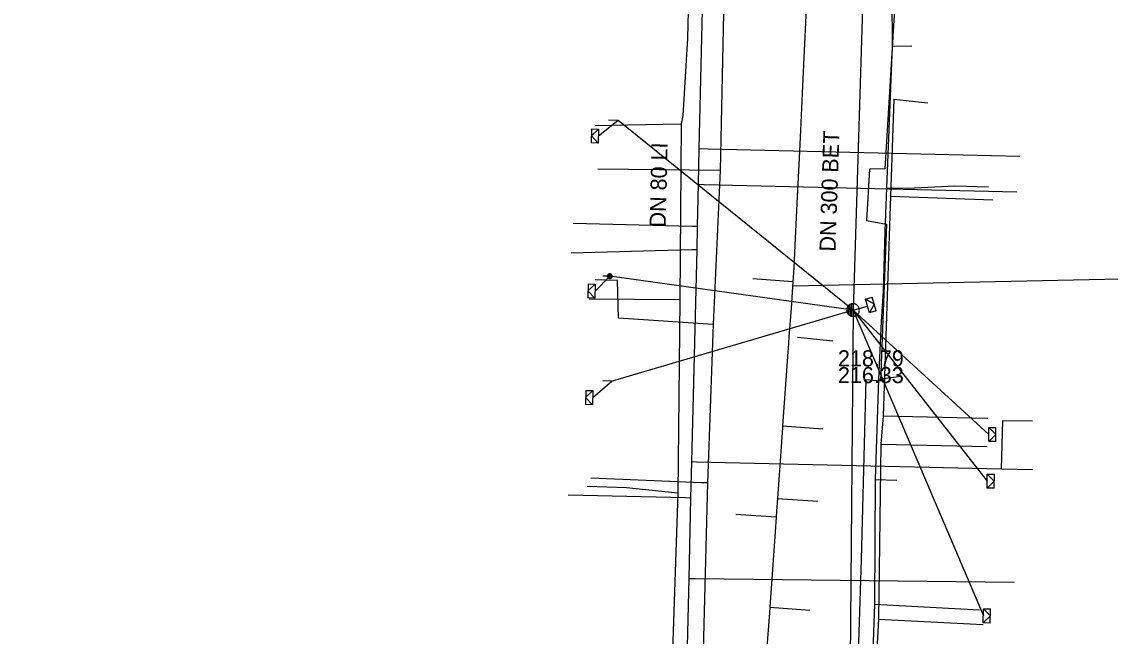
# Model space of a CAD drawing. Extents: x -596024 to -594475, y -1163820 to -1161957.
# Drawn here: x -595840.9 to -595786.8, y -1163039.3 to -1163008.8 of the extents above; entities that cross this region are included whole.
import ezdxf

# ---------------------------------------------------------------- set-up
doc = ezdxf.new("R2010")
doc.units = 0
for name, color, linetype in [('13', 7, 'Continuous'), ('31', 7, 'Continuous'), ('Vrstva 12', 7, 'Continuous'), ('Vrstva 13', 7, 'Continuous'), ('Vrstva 15', 7, 'Continuous'), ('Vrstva 16', 7, 'Continuous'), ('Vrstva 25', 7, 'Continuous'), ('Vrstva 43', 7, 'Continuous'), ('Vrstva 51', 7, 'Continuous'), ('Vrstva 55', 7, 'Continuous'), ('Vrstva 9', 7, 'Continuous')]:
    doc.layers.add(name, color=color, linetype=linetype)

# ---------------------------------------------------------------- blocks, each defined once
blk = doc.blocks.new('NN630')
at = {"layer": '31'}
for points in [[(-0.003, -0.7), (-0.703, 0)], [(-0.703, -0.7), (-0.703, 0), (0.697, 0), (0.697, -0.7)], [(-0.003, -0.7), (0.697, 0)], [(-0.703, -0.7), (0.697, -0.7)]]:
    blk.add_lwpolyline(points, dxfattribs=at)
blk = doc.blocks.new('NN510')
at = {"layer": '13'}
blk.add_lwpolyline([(0.001, 0.002), (0.001, 0.939)], dxfattribs=at)
blk = doc.blocks.new('NN500')
at = {"layer": '13'}
for points in [[(-0.001, -0.235), (0.023, -0.234), (0.048, -0.23), (0.071, -0.224), (0.094, -0.215), (0.116, -0.204), (0.137, -0.191), (0.156, -0.175), (0.173, -0.158), (0.189, -0.139), (0.202, -0.118), (0.213, -0.096), (0.222, -0.073), (0.229, -0.049), (0.232, -0.025), (0.234, 0), (0.232, 0.024), (0.229, 0.048), (0.222, 0.072), (0.213, 0.095), (0.202, 0.117), (0.189, 0.138), (0.173, 0.157), (0.156, 0.174), (0.137, 0.19), (0.116, 0.203), (0.094, 0.214), (0.071, 0.223), (0.048, 0.229), (0.023, 0.233), (-0.001, 0.235), (-0.026, 0.233), (-0.05, 0.229), (-0.074, 0.223), (-0.097, 0.214), (-0.119, 0.203), (-0.139, 0.19), (-0.158, 0.174), (-0.176, 0.157), (-0.191, 0.138), (-0.205, 0.117), (-0.216, 0.095), (-0.225, 0.072), (-0.231, 0.048), (-0.235, 0.024), (-0.236, 0), (-0.235, -0.025), (-0.231, -0.049), (-0.225, -0.073), (-0.216, -0.096), (-0.205, -0.118), (-0.191, -0.139), (-0.176, -0.158), (-0.158, -0.175), (-0.139, -0.191), (-0.119, -0.204), (-0.097, -0.215), (-0.074, -0.224), (-0.05, -0.23), (-0.026, -0.234), (-0.001, -0.235)], [(-0.001, -0.235), (0.023, -0.234), (0.048, -0.23), (0.071, -0.224), (0.094, -0.215), (0.116, -0.204), (0.137, -0.191), (0.156, -0.175), (0.173, -0.158), (0.189, -0.139), (0.202, -0.118), (0.213, -0.096), (0.222, -0.073), (0.229, -0.049), (0.232, -0.025), (0.234, 0), (0.232, 0.024), (0.229, 0.048), (0.222, 0.072), (0.213, 0.095), (0.202, 0.117), (0.189, 0.138), (0.173, 0.157), (0.156, 0.174), (0.137, 0.19), (0.116, 0.203), (0.094, 0.214), (0.071, 0.223), (0.048, 0.229), (0.023, 0.233), (-0.001, 0.235), (-0.026, 0.233), (-0.05, 0.229), (-0.074, 0.223), (-0.097, 0.214), (-0.119, 0.203), (-0.139, 0.19), (-0.158, 0.174), (-0.176, 0.157), (-0.191, 0.138), (-0.205, 0.117), (-0.216, 0.095), (-0.225, 0.072), (-0.231, 0.048), (-0.235, 0.024), (-0.236, 0), (-0.235, -0.025), (-0.231, -0.049), (-0.225, -0.073), (-0.216, -0.096), (-0.205, -0.118), (-0.191, -0.139), (-0.176, -0.158), (-0.158, -0.175), (-0.139, -0.191), (-0.119, -0.204), (-0.097, -0.215), (-0.074, -0.224), (-0.05, -0.23), (-0.026, -0.234), (-0.001, -0.235)], [(-0.001, -0.206), (0.02, -0.205), (0.041, -0.201), (0.062, -0.196), (0.082, -0.188), (0.101, -0.178), (0.12, -0.167), (0.136, -0.153), (0.151, -0.138), (0.165, -0.121), (0.177, -0.103), (0.186, -0.084), (0.194, -0.064), (0.2, -0.043), (0.203, -0.022), (0.204, 0), (0.203, 0.021), (0.2, 0.042), (0.194, 0.063), (0.186, 0.083), (0.177, 0.102), (0.165, 0.12), (0.151, 0.137), (0.136, 0.152), (0.12, 0.166), (0.101, 0.177), (0.082, 0.187), (0.062, 0.195), (0.041, 0.2), (0.02, 0.204), (-0.001, 0.205), (-0.023, 0.204), (-0.044, 0.2), (-0.065, 0.195), (-0.085, 0.187), (-0.104, 0.177), (-0.122, 0.166), (-0.139, 0.152), (-0.154, 0.137), (-0.167, 0.12), (-0.179, 0.102), (-0.189, 0.083), (-0.197, 0.063), (-0.202, 0.042), (-0.205, 0.021), (-0.207, 0), (-0.205, -0.022), (-0.202, -0.043), (-0.197, -0.064), (-0.189, -0.084), (-0.179, -0.103), (-0.167, -0.121), (-0.154, -0.138), (-0.139, -0.153), (-0.122, -0.167), (-0.104, -0.178), (-0.085, -0.188), (-0.065, -0.196), (-0.044, -0.201), (-0.023, -0.205), (-0.001, -0.206)], [(-0.001, -0.176), (0.017, -0.175), (0.035, -0.172), (0.053, -0.168), (0.07, -0.161), (0.087, -0.153), (0.102, -0.143), (0.116, -0.131), (0.129, -0.118), (0.141, -0.104), (0.151, -0.088), (0.159, -0.072), (0.166, -0.055), (0.171, -0.037), (0.174, -0.019), (0.175, 0), (0.174, 0.018), (0.171, 0.036), (0.166, 0.054), (0.159, 0.071), (0.151, 0.087), (0.141, 0.103), (0.129, 0.117), (0.116, 0.13), (0.102, 0.142), (0.087, 0.152), (0.07, 0.16), (0.053, 0.167), (0.035, 0.172), (0.017, 0.174), (-0.001, 0.175), (-0.02, 0.174), (-0.038, 0.172), (-0.056, 0.167), (-0.073, 0.16), (-0.089, 0.152), (-0.105, 0.142), (-0.119, 0.13), (-0.132, 0.117), (-0.143, 0.103), (-0.153, 0.087), (-0.162, 0.071), (-0.168, 0.054), (-0.173, 0.036), (-0.176, 0.018), (-0.177, 0), (-0.176, -0.019), (-0.173, -0.037), (-0.168, -0.055), (-0.162, -0.072), (-0.153, -0.088), (-0.143, -0.104), (-0.132, -0.118), (-0.119, -0.131), (-0.105, -0.143), (-0.089, -0.153), (-0.073, -0.161), (-0.056, -0.168), (-0.038, -0.172), (-0.02, -0.175), (-0.001, -0.176)], [(-0.001, -0.147), (0.014, -0.146), (0.029, -0.143), (0.044, -0.139), (0.058, -0.134), (0.072, -0.127), (0.085, -0.119), (0.097, -0.109), (0.107, -0.098), (0.117, -0.086), (0.125, -0.073), (0.132, -0.06), (0.138, -0.046), (0.142, -0.031), (0.144, -0.016), (0.145, 0), (0.144, 0.015), (0.142, 0.03), (0.138, 0.045), (0.132, 0.059), (0.125, 0.073), (0.117, 0.086), (0.107, 0.097), (0.097, 0.108), (0.085, 0.118), (0.072, 0.126), (0.058, 0.133), (0.044, 0.139), (0.029, 0.143), (0.014, 0.145), (-0.001, 0.146), (-0.017, 0.145), (-0.032, 0.143), (-0.046, 0.139), (-0.061, 0.133), (-0.074, 0.126), (-0.087, 0.118), (-0.099, 0.108), (-0.11, 0.097), (-0.119, 0.086), (-0.128, 0.073), (-0.135, 0.059), (-0.14, 0.045), (-0.144, 0.03), (-0.147, 0.015), (-0.147, 0), (-0.147, -0.016), (-0.144, -0.031), (-0.14, -0.046), (-0.135, -0.06), (-0.128, -0.073), (-0.119, -0.086), (-0.11, -0.098), (-0.099, -0.109), (-0.087, -0.119), (-0.074, -0.127), (-0.061, -0.134), (-0.046, -0.139), (-0.032, -0.143), (-0.017, -0.146), (-0.001, -0.147)], [(-0.001, -0.117), (0.011, -0.116), (0.023, -0.114), (0.035, -0.111), (0.046, -0.107), (0.057, -0.101), (0.067, -0.095), (0.077, -0.087), (0.085, -0.078), (0.093, -0.069), (0.1, -0.059), (0.105, -0.048), (0.11, -0.036), (0.113, -0.025), (0.115, -0.013), (0.115, 0), (0.115, 0.012), (0.113, 0.024), (0.11, 0.036), (0.105, 0.047), (0.1, 0.058), (0.093, 0.068), (0.085, 0.078), (0.077, 0.086), (0.067, 0.094), (0.057, 0.101), (0.046, 0.106), (0.035, 0.11), (0.023, 0.114), (0.011, 0.116), (-0.001, 0.116), (-0.013, 0.116), (-0.025, 0.114), (-0.037, 0.11), (-0.049, 0.106), (-0.059, 0.101), (-0.07, 0.094), (-0.079, 0.086), (-0.088, 0.078), (-0.096, 0.068), (-0.102, 0.058), (-0.108, 0.047), (-0.112, 0.036), (-0.115, 0.024), (-0.117, 0.012), (-0.118, 0), (-0.117, -0.013), (-0.115, -0.025), (-0.112, -0.036), (-0.108, -0.048), (-0.102, -0.059), (-0.096, -0.069), (-0.088, -0.078), (-0.079, -0.087), (-0.07, -0.095), (-0.059, -0.101), (-0.049, -0.107), (-0.037, -0.111), (-0.025, -0.114), (-0.013, -0.116), (-0.001, -0.117)], [(-0.001, -0.087), (0.008, -0.087), (0.017, -0.085), (0.026, -0.083), (0.034, -0.08), (0.042, -0.076), (0.05, -0.071), (0.057, -0.065), (0.063, -0.059), (0.069, -0.051), (0.074, -0.044), (0.078, -0.036), (0.081, -0.027), (0.084, -0.019), (0.085, -0.01), (0.086, 0), (0.085, 0.009), (0.084, 0.018), (0.081, 0.026), (0.078, 0.035), (0.074, 0.043), (0.069, 0.051), (0.063, 0.058), (0.057, 0.064), (0.05, 0.07), (0.042, 0.075), (0.034, 0.079), (0.026, 0.082), (0.017, 0.085), (0.008, 0.086), (-0.001, 0.087), (-0.01, 0.086), (-0.019, 0.085), (-0.028, 0.082), (-0.037, 0.079), (-0.045, 0.075), (-0.052, 0.07), (-0.059, 0.064), (-0.066, 0.058), (-0.072, 0.051), (-0.077, 0.043), (-0.081, 0.035), (-0.084, 0.026), (-0.086, 0.018), (-0.088, 0.009), (-0.088, 0), (-0.088, -0.01), (-0.086, -0.019), (-0.084, -0.027), (-0.081, -0.036), (-0.077, -0.044), (-0.072, -0.052), (-0.066, -0.059), (-0.059, -0.065), (-0.052, -0.071), (-0.045, -0.076), (-0.037, -0.08), (-0.028, -0.083), (-0.019, -0.085), (-0.01, -0.087), (-0.001, -0.087)], [(-0.001, -0.058), (0.005, -0.057), (0.011, -0.056), (0.016, -0.055), (0.022, -0.053), (0.027, -0.05), (0.032, -0.047), (0.037, -0.043), (0.041, -0.039), (0.045, -0.034), (0.048, -0.029), (0.051, -0.024), (0.053, -0.018), (0.055, -0.012), (0.056, -0.006), (0.056, 0), (0.056, 0.006), (0.055, 0.011), (0.053, 0.017), (0.051, 0.023), (0.048, 0.028), (0.045, 0.033), (0.041, 0.038), (0.037, 0.042), (0.032, 0.046), (0.027, 0.049), (0.022, 0.052), (0.016, 0.054), (0.011, 0.056), (0.005, 0.057), (-0.001, 0.057), (-0.007, 0.057), (-0.013, 0.056), (-0.019, 0.054), (-0.025, 0.052), (-0.03, 0.049), (-0.035, 0.046), (-0.04, 0.042), (-0.044, 0.038), (-0.048, 0.033), (-0.051, 0.028), (-0.054, 0.023), (-0.056, 0.017), (-0.057, 0.011), (-0.058, 0.006), (-0.059, 0), (-0.058, -0.006), (-0.057, -0.012), (-0.056, -0.018), (-0.054, -0.024), (-0.051, -0.029), (-0.048, -0.034), (-0.044, -0.039), (-0.04, -0.043), (-0.035, -0.047), (-0.03, -0.05), (-0.025, -0.053), (-0.019, -0.055), (-0.013, -0.056), (-0.007, -0.057), (-0.001, -0.058)], [(-0.001, -0.028), (0.002, -0.028), (0.005, -0.028), (0.007, -0.027), (0.01, -0.026), (0.013, -0.024), (0.015, -0.023), (0.017, -0.021), (0.019, -0.019), (0.021, -0.017), (0.023, -0.014), (0.024, -0.012), (0.025, -0.009), (0.026, -0.006), (0.026, -0.003), (0.027, 0), (0.026, 0.002), (0.026, 0.005), (0.025, 0.008), (0.024, 0.011), (0.023, 0.013), (0.021, 0.016), (0.019, 0.018), (0.017, 0.02), (0.015, 0.022), (0.013, 0.024), (0.01, 0.025), (0.007, 0.026), (0.005, 0.027), (0.002, 0.027), (-0.001, 0.027), (-0.004, 0.027), (-0.007, 0.027), (-0.01, 0.026), (-0.012, 0.025), (-0.015, 0.024), (-0.018, 0.022), (-0.02, 0.02), (-0.022, 0.018), (-0.024, 0.016), (-0.025, 0.013), (-0.027, 0.011), (-0.028, 0.008), (-0.028, 0.005), (-0.029, 0.002), (-0.029, 0), (-0.029, -0.003), (-0.028, -0.006), (-0.028, -0.009), (-0.027, -0.012), (-0.025, -0.014), (-0.024, -0.017), (-0.022, -0.019), (-0.02, -0.021), (-0.018, -0.023), (-0.015, -0.024), (-0.012, -0.026), (-0.01, -0.027), (-0.007, -0.028), (-0.004, -0.028), (-0.001, -0.028)], [(0.234, 0), (0.704, 0)]]:
    blk.add_lwpolyline(points, dxfattribs=at)
blk = doc.blocks.new('NN440')
at = {"layer": '13'}
for points in [[(-0.631, 0), (0.629, 0)], [(0.631, -0.004), (0.627, 0.062), (0.617, 0.127), (0.6, 0.191), (0.577, 0.252), (0.547, 0.311), (0.511, 0.366), (0.469, 0.417), (0.423, 0.464), (0.371, 0.505), (0.316, 0.542), (0.257, 0.571), (0.196, 0.595), (0.132, 0.612), (0.067, 0.622), (0.001, 0.626), (-0.065, 0.622), (-0.13, 0.612), (-0.194, 0.595), (-0.255, 0.571), (-0.314, 0.542), (-0.369, 0.505), (-0.42, 0.464), (-0.467, 0.417), (-0.509, 0.366), (-0.544, 0.311), (-0.574, 0.252), (-0.598, 0.191), (-0.615, 0.127), (-0.626, 0.062), (-0.629, -0.004), (-0.626, -0.07), (-0.615, -0.135), (-0.598, -0.199), (-0.574, -0.26), (-0.544, -0.319), (-0.509, -0.374), (-0.467, -0.426), (-0.42, -0.472), (-0.369, -0.514), (-0.314, -0.55), (-0.255, -0.58), (-0.194, -0.603), (-0.13, -0.62), (-0.065, -0.631), (0.001, -0.634), (0.067, -0.631), (0.132, -0.62), (0.196, -0.603), (0.257, -0.58), (0.316, -0.55), (0.371, -0.514), (0.423, -0.472), (0.469, -0.426), (0.511, -0.374), (0.547, -0.319), (0.577, -0.26), (0.6, -0.199), (0.617, -0.135), (0.627, -0.07), (0.631, -0.004)], [(-0.601, -0.177), (0.57, -0.177)], [(-0.513, -0.325), (0.501, -0.325)], [(-0.375, -0.473), (0.353, -0.473)]]:
    blk.add_lwpolyline(points, dxfattribs=at)

msp = doc.modelspace()

# ---------------------------------------------------------------- linework, layer by layer
at = {"layer": 'Vrstva 12'}
msp.add_lwpolyline([(-595802.602, -1163021.887), (-595781.677, -1163021.438), (-595781.191, -1163010.631)], dxfattribs=at)
at = {"layer": 'Vrstva 13'}
for points in [[(-595806.635, -1162983.978), (-595806.541, -1162984.987), (-595806.844, -1162997.811), (-595807.252, -1163015.074), (-595807.294, -1163016.84), (-595807.341, -1163018.943), (-595807.361, -1163020.108), (-595807.62, -1163030.62), (-595807.663, -1163032.431), (-595807.757, -1163036.42), (-595807.82, -1163039.12), (-595807.951, -1163044.676), (-595808.029, -1163047.947), (-595808.115, -1163051.598), (-595809.241, -1163056.558)], [(-595807.252, -1163015.074), (-595806.788, -1163015.085), (-595791.325, -1163015.45)], [(-595807.294, -1163016.84), (-595806.985, -1163016.847), (-595791.461, -1163017.214)], [(-595807.341, -1163018.943), (-595807.584, -1163018.937), (-595813.498, -1163018.798)], [(-595807.361, -1163020.108), (-595807.607, -1163020.104), (-595813.598, -1163020.262)], [(-595792.226, -1163030.983), (-595792.169, -1163028.571), (-595790.682, -1163028.592)], [(-595807.62, -1163030.62), (-595807.378, -1163030.626), (-595792.226, -1163030.983), (-595790.698, -1163031.019)], [(-595807.663, -1163032.431), (-595807.916, -1163032.425), (-595813.742, -1163032.288)], [(-595807.757, -1163036.42), (-595807.444, -1163036.431), (-595791.597, -1163036.606)]]:
    msp.add_lwpolyline(points, dxfattribs=at)
at = {"layer": 'Vrstva 16'}
for points in [[(-595805.65, -1162986.36), (-595805.61, -1162989.38), (-595805.63, -1162989.55), (-595806.19, -1163016.16), (-595806.54, -1163023.81), (-595806.82, -1163031.68), (-595807.18, -1163045.1), (-595807.49, -1163054.49), (-595807.54, -1163055.81), (-595807.75, -1163058.15)], [(-595797.58, -1163012.61), (-595797.74, -1163017.44), (-595798.11, -1163028.35), (-595798.22, -1163029.75), (-595798.34, -1163038.45), (-595798.8, -1163047.04), (-595798.85, -1163055.25), (-595807.49, -1163054.49)], [(-595797.58, -1163012.61), (-595795.887, -1163012.792)], [(-595806.19, -1163016.16), (-595812.28, -1163016.1)], [(-595797.74, -1163017.44), (-595792.66, -1163017.61)], [(-595806.54, -1163023.81), (-595811.24, -1163023.49), (-595811.3, -1163021.63), (-595812.4, -1163021.59)], [(-595798.11, -1163028.35), (-595794.447, -1163028.435), (-595792.91, -1163028.47)], [(-595798.22, -1163029.75), (-595792.94, -1163029.87)], [(-595806.82, -1163031.68), (-595807.12, -1163031.68), (-595812.62, -1163031.45)], [(-595798.34, -1163038.45), (-595793.14, -1163038.72)]]:
    msp.add_lwpolyline(points, dxfattribs=at)
at = {"layer": 'Vrstva 25'}
for p, q in [((-595807.524, -1162998.474), (-595807.816, -1163009.585)), ((-595797.681, -1163007.177), (-595797.654, -1163009.979)), ((-595807.816, -1163009.585), (-595808.052, -1163013.429)), ((-595797.654, -1163009.979), (-595797.931, -1163017.023)), ((-595797.654, -1163009.979), (-595796.684, -1163009.97)), ((-595808.052, -1163013.429), (-595808.129, -1163013.85)), ((-595810.793, -1163013.912), (-595812.408, -1163013.932)), ((-595808.129, -1163013.85), (-595810.793, -1163013.912)), ((-595808.129, -1163013.85), (-595808.202, -1163022.576)), ((-595797.931, -1163017.023), (-595798.02, -1163019.174)), ((-595797.931, -1163017.023), (-595796.873, -1163017.044)), ((-595796.873, -1163017.044), (-595794.546, -1163016.913)), ((-595794.546, -1163016.913), (-595792.868, -1163016.971)), ((-595798.02, -1163019.174), (-595798.109, -1163022.152)), ((-595798.109, -1163022.152), (-595798.199, -1163023.655)), ((-595808.202, -1163022.576), (-595812.701, -1163022.555)), ((-595808.202, -1163022.576), (-595808.297, -1163032.181)), ((-595798.199, -1163023.655), (-595798.334, -1163026.52)), ((-595798.334, -1163026.52), (-595797.217, -1163026.379)), ((-595798.334, -1163026.52), (-595798.499, -1163031.516)), ((-595810.848, -1163031.927), (-595812.798, -1163031.859)), ((-595798.499, -1163031.516), (-595798.54, -1163037.703)), ((-595798.499, -1163031.516), (-595797.424, -1163031.543)), ((-595808.297, -1163032.181), (-595810.848, -1163031.927)), ((-595808.297, -1163032.181), (-595808.991, -1163052.616)), ((-595798.54, -1163037.703), (-595798.849, -1163046.355)), ((-595798.54, -1163037.703), (-595793.324, -1163037.977))]:
    msp.add_line(p, q, dxfattribs=at)
at = {"layer": 'Vrstva 51'}
for points in [[(-595798.693, -1162993.822), (-595798.752, -1162995.701), (-595799.6, -1163023.09), (-595799.91, -1163059.77)], [(-595799.6, -1163023.09), (-595811.266, -1163013.668), (-595812.241, -1163014.452)], [(-595799.6, -1163023.09), (-595811.679, -1163021.406), (-595812.411, -1163022.15)], [(-595799.6, -1163023.09), (-595811.555, -1163026.62), (-595812.528, -1163027.446)], [(-595799.6, -1163023.09), (-595798.885, -1163022.891)], [(-595799.6, -1163023.09), (-595792.94, -1163031.59)], [(-595799.6, -1163023.09), (-595792.86, -1163029.27)], [(-595799.6, -1163023.09), (-595793.131, -1163038.282)]]:
    msp.add_lwpolyline(points, dxfattribs=at)
at = {"layer": 'Vrstva 55'}
msp.add_lwpolyline([(-595797.46, -1163006.77), (-595798.03, -1163016.07), (-595798.79, -1163016.09), (-595798.94, -1163018.65), (-595797.94, -1163018.83), (-595798.24, -1163026.62), (-595798.97, -1163026.56), (-595799.19, -1163035.49), (-595799.87, -1163056.64), (-595798.21, -1163060.99), (-595798.971, -1163064.383), (-595799.566, -1163065.238), (-595800.049, -1163065.684), (-595800.644, -1163065.759), (-595809.346, -1163063.788), (-595818.941, -1163062.04), (-595836.494, -1163057.986), (-595839.433, -1163057.21), (-595841.775, -1163057.094), (-595863.976, -1163051.404), (-595888.9, -1163044.67)], dxfattribs=at)
at = {"layer": 'Vrstva 9'}
for p, q in [((-595802.588, -1163021.686), (-595804.583, -1163021.548)), ((-595802.352, -1163024.444), (-595800.61, -1163024.62)), ((-595803.095, -1163028.845), (-595801.1, -1163028.984)), ((-595803.35, -1163032.445), (-595801.355, -1163032.587)), ((-595803.417, -1163033.384), (-595805.412, -1163033.244)), ((-595803.733, -1163037.852), (-595801.738, -1163037.994))]:
    msp.add_line(p, q, dxfattribs=at)
for points in [[(-595801.773, -1163004.934), (-595802.109, -1163011.966), (-595802.214, -1163014.162), (-595802.28, -1163015.552), (-595802.371, -1163017.451), (-595802.503, -1163020.231), (-595802.54, -1163021)], [(-595802.54, -1163021), (-595802.588, -1163021.686), (-595802.68, -1163022.99)], [(-595802.68, -1163022.99), (-595802.782, -1163024.428), (-595802.825, -1163025.016), (-595802.835, -1163025.145), (-595802.854, -1163025.408), (-595803.095, -1163028.845), (-595803.102, -1163028.949), (-595803.35, -1163032.445), (-595803.395, -1163033.081), (-595803.417, -1163033.384), (-595803.469, -1163034.114), (-595803.733, -1163037.852), (-595803.752, -1163038.127), (-595803.889, -1163040.05), (-595803.926, -1163040.57), (-595804.094, -1163042.94), (-595804.122, -1163043.331), (-595804.215, -1163044.645), (-595804.252, -1163045.168), (-595805.045, -1163056.362), (-595805.07, -1163056.72), (-595805.296, -1163059.905), (-595805.48, -1163062.5)]]:
    msp.add_lwpolyline(points, dxfattribs=at)

# ---------------------------------------------------------------- block references
at = {"layer": 'Vrstva 43', "xscale": 0.5, "yscale": 0.5}
for name, p, rotation in [('NN510', (-595811.266, -1163013.668), 89), ('NN630', (-595812.241, -1163014.45), -91), ('NN500', (-595811.679, -1163021.406), 179), ('NN630', (-595812.411, -1163022.149), -91), ('NN630', (-595798.885, -1163022.891), 106), ('NN440', (-595799.6, -1163023.09), -91), ('NN510', (-595811.555, -1163026.621), 89), ('NN630', (-595812.528, -1163027.445), -91), ('NN630', (-595792.859, -1163029.27), 89), ('NN630', (-595792.939, -1163031.59), 89), ('NN630', (-595793.131, -1163038.282), 89)]:
    msp.add_blockref(name, p, dxfattribs=dict(at, rotation=rotation))

# ---------------------------------------------------------------- texts
at = {"layer": 'Vrstva 12'}
for s, rotation, p in [('DN 300 BET', 88.0636, (-595800.473, -1163020.197)), ('218.79', 359.9924, (-595800.35, -1163025.889)), ('216.33', 359.9924, (-595800.351, -1163026.721))]:
    msp.add_text(s, height=0.8, rotation=rotation, dxfattribs=at).set_placement(p)
at = {"layer": 'Vrstva 15'}
msp.add_text('DN 80 LI', height=0.8, rotation=88.6366, dxfattribs=at).set_placement((-595808.905, -1163018.998))

doc.saveas('drawing.dxf')
